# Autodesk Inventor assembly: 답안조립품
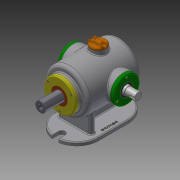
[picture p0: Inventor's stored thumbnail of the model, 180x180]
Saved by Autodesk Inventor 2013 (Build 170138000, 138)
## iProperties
Created: 2018-02
Part Number: 답안조립품
Document SubType Name: Assembly
Designer: Administrator
Mass: 7552.26 g
Surface Area: 3901.66 cm^2
Volume: 1791.91 cm^3
Density: 4.21465 g/cm^3
Author: Administrator
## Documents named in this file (16)
- C:\Users\Administrator\Desktop\380208V1005\답안조립품.iam
- C:\Users\Administrator\Desktop\380208V1005\본체.ipt
- C:\Users\Administrator\Desktop\380208V1005\슬라이드.ipt
- C:\Users\Administrator\Desktop\380208V1005\슬라이드 커버.ipt
- C:\Users\Administrator\Desktop\380208V1005\부시.ipt
- C:\Users\Administrator\Desktop\380208V1005\본체커버.ipt
- C:\Users\Administrator\Desktop\380208V1005\상부 캡.ipt
- C:\Users\Administrator\Desktop\380208V1005\볼트 M4.ipt
- C:\Users\Administrator\Desktop\380208V1005\축 커버-2.ipt
- C:\Users\Administrator\Desktop\380208V1005\베어링 6205.ipt
- 베어링 6205.ipt
- C:\Users\Administrator\Desktop\380208V1005\편심축.ipt
- C:\Users\Administrator\Desktop\380208V1005\축 커버-1.ipt
- C:\Users\Administrator\Desktop\380208V1005\오일실.ipt
- 오일실.ipt
- C:\Users\Administrator\Desktop\380208V1005\가변스프링4.ipt
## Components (1 placed, 1 different names)
1. 가변스프링4:1
